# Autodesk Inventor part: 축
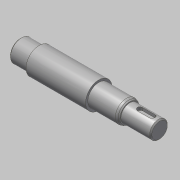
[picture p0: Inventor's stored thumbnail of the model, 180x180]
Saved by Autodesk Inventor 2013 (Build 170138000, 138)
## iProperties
Created: 2016-06
Part Number: 축
Material: 강철, 연강
Document SubType Name: Modeling
Designer: mduedu
Density: 7.86 g/cm^3
Author: mduedu
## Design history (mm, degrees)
sketch "스케치1"
  geometry: L1 (-63, 0)-(63, 0); L2 (-63, 0)-(-63, 10); L3 (-63, 10)-(-46, 10); L4 (-46, 10)-(-46, 12); L5 (-46, 12)-(8, 12); L6 (8, 12)-(8, 10); L7 (8, 10)-(36, 10); L8 (36, 10)-(36, 8); L9 (36, 8)-(63, 8); L10 (63, 8)-(63, 0); 2 further points
  constraints: 20 end point, 5 parallel, 2 perpendicular, 1 coincident, 1 collinear, 1 horizontal, 1 midpoint, 1 vertical
  dimensions: "d0" = 126 distance of L1.start L1.end; "d2" = 16 diameter of L9 L1; "d3" = 20 diameter of L7 L1; "d4" = 24 diameter of L5 L1; "d5" = 20 diameter of L3 L1; "d6" = 17 distance of L2.end L3.end; "d7" = 27 distance of L8.end L9.end; "d8" = 55 distance from line of L5.end L10
revolve "회전1" sketch "스케치1" stored, may be unused: angle "d9" = 90 deg
chamfer "모따기1" distance "d10" = 2; stored, may be unused: second distance "d11" = 2, angle "d12" = 30 deg
fillet "모깎기1" dims "d13" = 4
node "작업 평면1"
sketch "스케치2"
  geometry: L1 (-4, 2.5)-(7, 2.5); L2 (7, -2.5)-(-4, -2.5); L3 (-4, 0)-(7, 0); L4 (-13.5, 8.845)-(-13.5, -8.845) reference; A1 r 2.5 centre (-4, 0) between (-4, 2.5) and (-4, -2.5); A2 r 2.5 centre (7, 0) between (7, -2.5) and (7, 2.5); 1 further point
  constraints: 6 end point, 4 point on circle, 3 tangent, 2 centre point, 2 parallel, 1 horizontal, 1 horizontal alignment
  dimensions: "d14" = 7 distance edge to line of A1 L4; "d15" = 5 distance between parallel lines of L2 L1; "d16" = 16 dimension on A2 A1
extrude "돌출1" cut sketch "스케치2" distance "d17" = 3; taper "d18" = 0 deg
chamfer "모따기2" distance "d19" = 1; stored, may be unused: second distance "d20" = 2, angle "d21" = 30 deg
sketch "스케치3"
  geometry: L1 (-36, -8)-(-62, -8) reference; L2 (-63, -7)-(-63, 7) reference; L3 (-39.5, -8)-(-41, -6.5); L4 (-41, -6.5)-(-41, -8); L5 (-39.5, -8)-(-41, -8); 1 further point
  constraints: 6 end point, 2 point on line, 1 collinear, 1 vertical
  dimensions: "d22" = 45 deg angle of L4 L3; "d23" = 22 distance between parallel lines of L2 L4; "d24" = 3 diameter of L3.start L4
revolve "회전2" stored, may be unused: angle "d25" = 90 deg
node "작업점1"
sketch "스케치4"
  geometry: 1 further point
hole "구멍1" sketch "스케치4" at (0, 0) diameter "d26" = 3.242; stored, may be unused: countersink angle "d30" = 90 deg, drill point angle "d32" = 120 deg; dims "d27" = 8, "d28" = 4, "d29" = 2, "d31" = 11
chamfer "모따기3" distance "d33" = 2; stored, may be unused: second distance "d34" = 2, angle "d35" = 30 deg
node "솔리드1"
